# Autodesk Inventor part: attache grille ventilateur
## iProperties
Created: 2011-01
Part Number: attache grille ventilateur
Document SubType Name: Modeling
Designer: eric
Density: 1 g/cm^3
Mass: 0.341774 g
Surface Area: 7.64586 cm^2
Volume: 0.341774 cm^3
Author: eric
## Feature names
1. Base1
